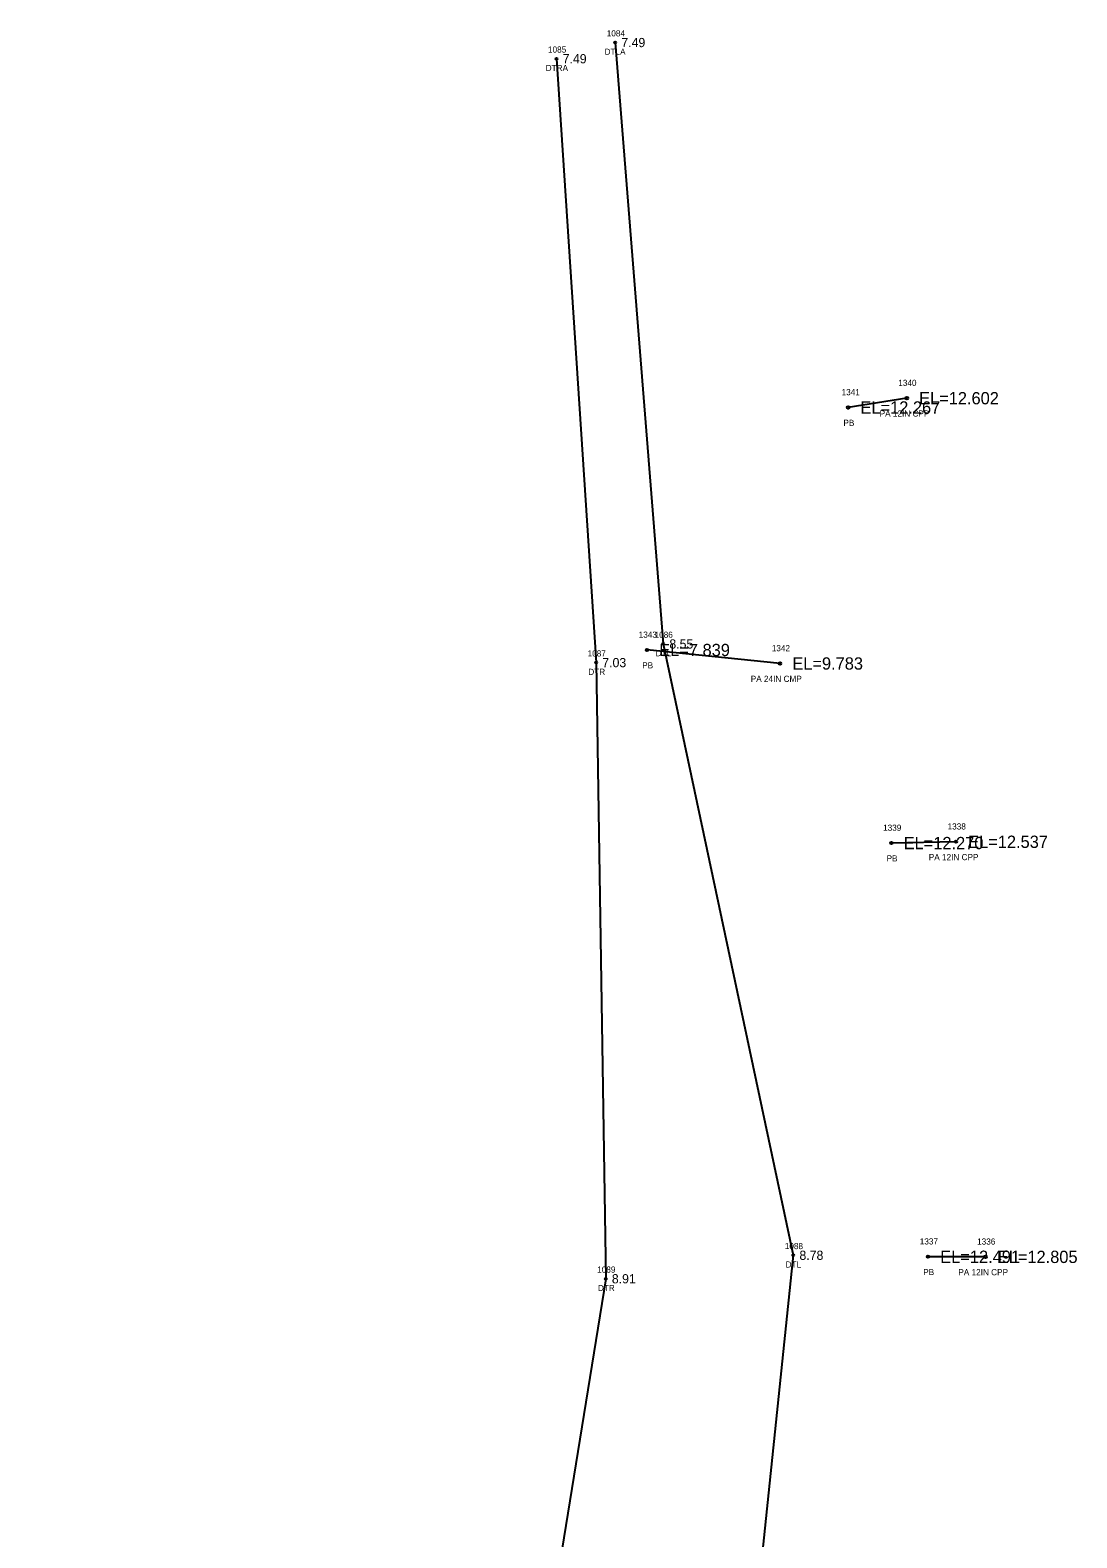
# Model space of a CAD drawing. Extents: x 2072307 to 2072993, y 127574 to 129736.
# Drawn here: x 2072308.2 to 2072478.9, y 128316.6 to 128562.3 of the extents above; entities that cross this region are included whole.
import ezdxf

# ---------------------------------------------------------------- set-up
doc = ezdxf.new("R2010")
doc.units = 0
for name, color, linetype in [('RD_EX_DR_Pipe', 7, 'Continuous'), ('RD_EX_DR_Pipe_txCode', 7, 'Continuous'), ('RD_EX_H2O', 7, 'Continuous'), ('RD_EX_H2O_txCode', 7, 'Continuous'), ('RD_EX_TX_H2O_ELEV', 7, 'Continuous'), ('RD_SMD_Locator', 7, 'Continuous'), ('RD_TX_Pipe_ElevEX', 7, 'Continuous')]:
    doc.layers.add(name, color=color, linetype=linetype)

msp = doc.modelspace()

# ---------------------------------------------------------------- linework, layer by layer
at = {"layer": 'RD_EX_DR_Pipe'}
for p, q in [((2072451.17, 128502.32), (2072441.61, 128500.81)), ((2072430.5, 128459.08), (2072408.8, 128461.28)), ((2072459.17, 128430.02), (2072448.65, 128429.81)), ((2072464, 128362.36), (2072454.62, 128362.38))]:
    msp.add_line(p, q, dxfattribs=at)
at = {"layer": 'RD_EX_H2O'}
for points in [[(2072403.62, 128560.29), (2072411.45, 128462.26), (2072432.66, 128362.62), (2072419.56, 128236.49), (2072406.7, 128177.6), (2072390.06, 128127.17), (2072380.51, 128114.72)], [(2072394.05, 128557.65), (2072400.51, 128459.22), (2072402.07, 128358.79), (2072383.51, 128244.18), (2072363.41, 128182.49), (2072364.78, 128146.69), (2072330.57, 128113.46), (2072324.79, 128105.03), (2072308.22, 128075.71)]]:
    msp.add_lwpolyline(points, dxfattribs=at)
at = {"layer": 'RD_SMD_Locator'}
for centre, radius in [((2072403.62, 128560.29), 0.15), ((2072394.05, 128557.65), 0.15), ((2072451.17, 128502.32), 0.2), ((2072441.61, 128500.81), 0.2), ((2072408.8, 128461.28), 0.2), ((2072411.45, 128462.26), 0.15), ((2072400.51, 128459.22), 0.15), ((2072430.5, 128459.08), 0.2), ((2072448.65, 128429.81), 0.2), ((2072459.17, 128430.02), 0.2), ((2072432.66, 128362.62), 0.15), ((2072454.62, 128362.38), 0.2), ((2072464, 128362.36), 0.2), ((2072402.07, 128358.79), 0.15)]:
    msp.add_circle(centre, radius, dxfattribs=at)

# ---------------------------------------------------------------- texts
at = {"layer": 'RD_EX_DR_Pipe_txCode'}
for s, p in [('1340', (2072449.78, 128504.32)), ('1341', (2072440.54, 128502.81)), ('PA 12IN CPP', (2072446.74, 128499.32)), ('PB', (2072440.83, 128497.81)), ('1343', (2072407.45, 128463.28)), ('1342', (2072429.15, 128461.08)), ('PB', (2072408.02, 128458.28)), ('PA 24IN CMP', (2072425.72, 128456.08)), ('1339', (2072447.3, 128431.81)), ('1338', (2072457.82, 128432.02)), ('PB', (2072447.87, 128426.81)), ('PA 12IN CPP', (2072454.75, 128427.02)), ('1337', (2072453.28, 128364.38)), ('1336', (2072462.63, 128364.36)), ('PB', (2072453.84, 128359.38)), ('PA 12IN CPP', (2072459.57, 128359.36))]:
    msp.add_text(s, height=1, dxfattribs=at).set_placement(p)
at = {"layer": 'RD_EX_H2O_txCode'}
for s, p in [('1084', (2072402.24, 128561.29)), ('1085', (2072392.66, 128558.65)), ('DTLA', (2072401.89, 128558.29)), ('DTRA', (2072392.29, 128555.65)), ('1086', (2072410.04, 128463.26)), ('1087', (2072399.12, 128460.22)), ('DTL', (2072410.21, 128460.26)), ('DTR', (2072399.24, 128457.22)), ('1088', (2072431.27, 128363.62)), ('1089', (2072400.68, 128359.79)), ('DTL', (2072431.41, 128360.62)), ('DTR', (2072400.8, 128356.79))]:
    msp.add_text(s, height=1, dxfattribs=at).set_placement(p)
at = {"layer": 'RD_EX_TX_H2O_ELEV'}
for s, p in [('7.49', (2072404.62, 128559.54)), ('7.49', (2072395.05, 128556.9)), ('8.55', (2072412.45, 128461.51)), ('7.03', (2072401.51, 128458.47)), ('8.78', (2072433.66, 128361.87)), ('8.91', (2072403.07, 128358.04))]:
    msp.add_text(s, height=1.5, dxfattribs=at).set_placement(p)
at = {"layer": 'RD_TX_Pipe_ElevEX'}
for s, p in [('EL=12.602', (2072453.17, 128501.32)), ('EL=12.267', (2072443.61, 128499.81)), ('EL=7.839', (2072410.8, 128460.28)), ('EL=9.783', (2072432.5, 128458.08)), ('EL=12.270', (2072450.65, 128428.81)), ('EL=12.537', (2072461.17, 128429.02)), ('EL=12.491', (2072456.62, 128361.38)), ('EL=12.805', (2072466, 128361.36))]:
    msp.add_text(s, height=2, dxfattribs=at).set_placement(p)

doc.saveas('drawing.dxf')
